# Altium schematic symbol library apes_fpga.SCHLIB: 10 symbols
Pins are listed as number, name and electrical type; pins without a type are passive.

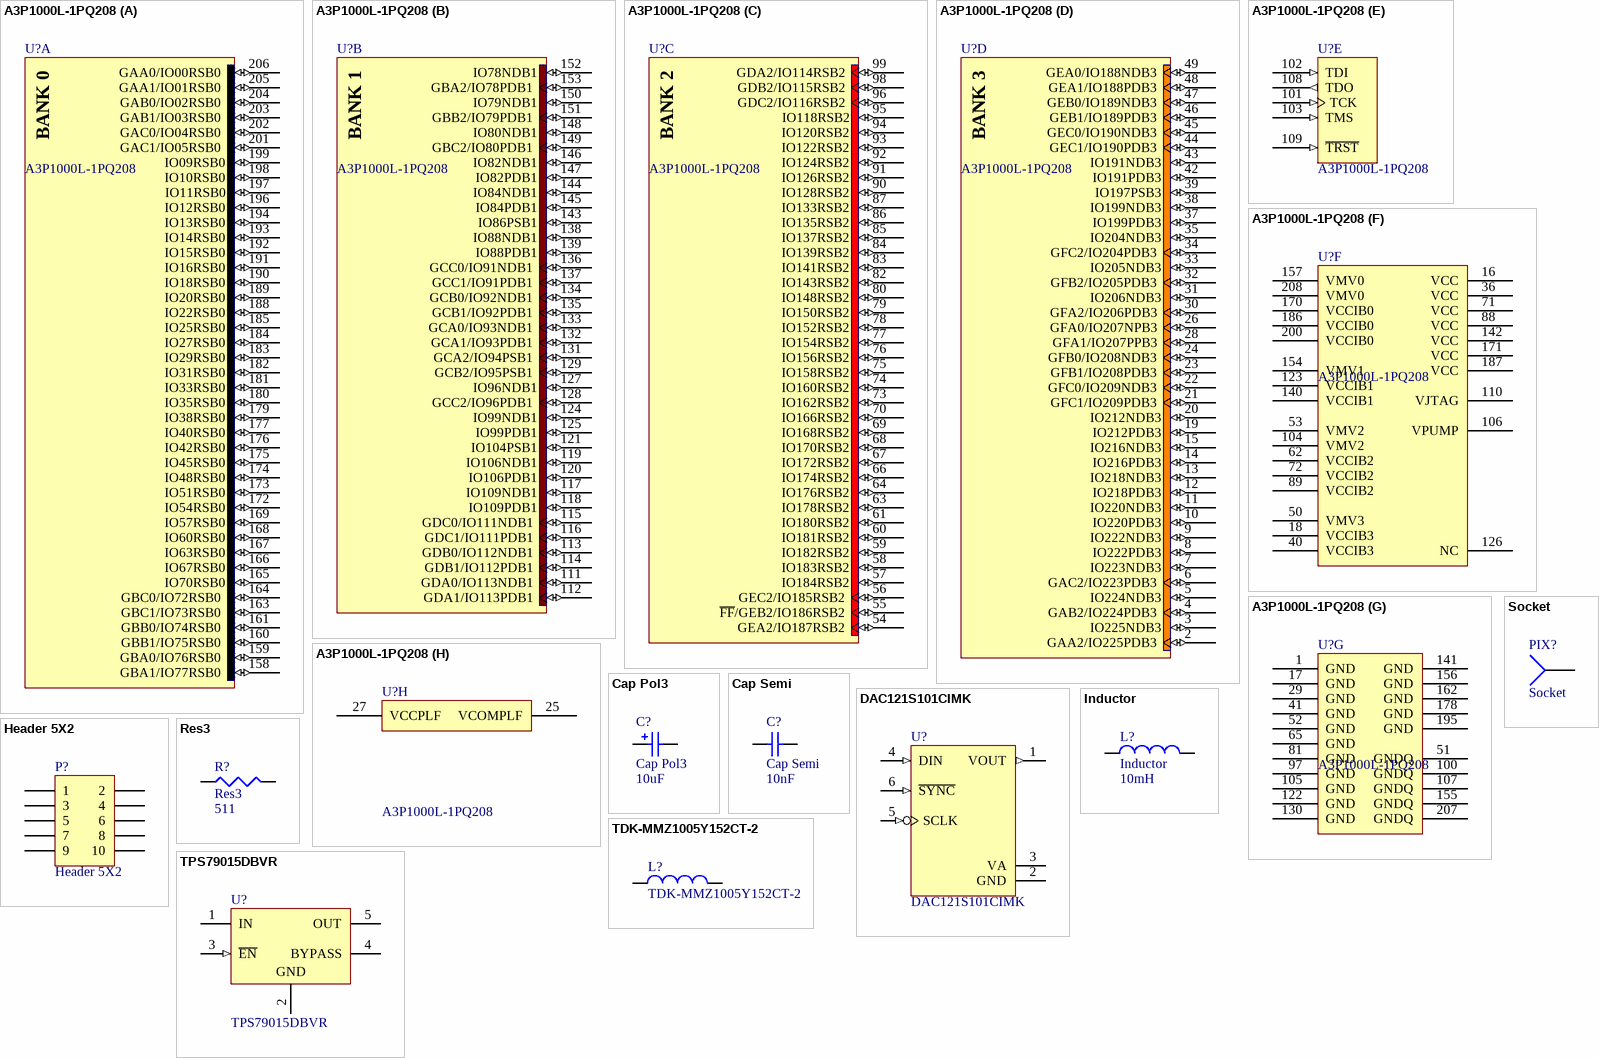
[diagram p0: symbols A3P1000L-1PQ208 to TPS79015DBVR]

## A3P1000L-1PQ208
designator U?
ProASIC3L Low-Power Flash Family FPGA, 154 User IOs, 1M System Gates, 144 Kbits RAM, 1 Kbit FlashROM, 1PLL, 208-Pin PQFP, Commercial Grade
footprint PQ208_N (Shrink QFP, 208-Leads, Body 28x28mm, Pitch 0.5mm, IPC Medium Density)
footprint PQ208_L (Shrink QFP, 208-Leads, Body 28x28mm, Pitch 0.5mm, IPC High Density)
footprint PQ208_M (Shrink QFP, 208-Leads, Body 28x28mm, Pitch 0.5mm, IPC Low Density)
part A pins: 158 GBA1/IO77RSB0 (io), 159 GBA0/IO76RSB0 (io), 160 GBB1/IO75RSB0 (io), 161 GBB0/IO74RSB0 (io), 163 GBC1/IO73RSB0 (io), 164 GBC0/IO72RSB0 (io), 165 IO70RSB0 (io), 166 IO67RSB0 (io), 167 IO63RSB0 (io), 168 IO60RSB0 (io), 169 IO57RSB0 (io), 172 IO54RSB0 (io), 173 IO51RSB0 (io), 174 IO48RSB0 (io), 175 IO45RSB0 (io), 176 IO42RSB0 (io), 177 IO40RSB0 (io), 179 IO38RSB0 (io), 180 IO35RSB0 (io), 181 IO33RSB0 (io), 182 IO31RSB0 (io), 183 IO29RSB0 (io), 184 IO27RSB0 (io), 185 IO25RSB0 (io), 188 IO22RSB0 (io), 189 IO20RSB0 (io), 190 IO18RSB0 (io), 191 IO16RSB0 (io), 192 IO15RSB0 (io), 193 IO14RSB0 (io), 194 IO13RSB0 (io), 196 IO12RSB0 (io), 197 IO11RSB0 (io), 198 IO10RSB0 (io), 199 IO09RSB0 (io), 201 GAC1/IO05RSB0 (io), 202 GAC0/IO04RSB0 (io), 203 GAB1/IO03RSB0 (io), 204 GAB0/IO02RSB0 (io), 205 GAA1/IO01RSB0 (io), 206 GAA0/IO00RSB0 (io)
part B pins: 111 GDA0/IO113NDB1 (io), 112 GDA1/IO113PDB1 (io), 113 GDB0/IO112NDB1 (io), 114 GDB1/IO112PDB1 (io), 115 GDC0/IO111NDB1 (io), 116 GDC1/IO111PDB1 (io), 117 IO109NDB1 (io), 118 IO109PDB1 (io), 119 IO106NDB1 (io), 120 IO106PDB1 (io), 121 IO104PSB1 (io), 124 IO99NDB1 (io), 125 IO99PDB1 (io), 127 IO96NDB1 (io), 128 GCC2/IO96PDB1 (io), 129 GCB2/IO95PSB1 (io), 131 GCA2/IO94PSB1 (io), 132 GCA1/IO93PDB1 (io), 133 GCA0/IO93NDB1 (io), 134 GCB0/IO92NDB1 (io), 135 GCB1/IO92PDB1 (io), 136 GCC0/IO91NDB1 (io), 137 GCC1/IO91PDB1 (io), 138 IO88NDB1 (io), 139 IO88PDB1 (io), 143 IO86PSB1 (io), 144 IO84NDB1 (io), 145 IO84PDB1 (io), 146 IO82NDB1 (io), 147 IO82PDB1 (io), 148 IO80NDB1 (io), 149 GBC2/IO80PDB1 (io), 150 IO79NDB1 (io), 151 GBB2/IO79PDB1 (io), 152 IO78NDB1 (io), 153 GBA2/IO78PDB1 (io)
part C pins: 54 GEA2/IO187RSB2 (io), 55 ~{FF}/GEB2/IO186RSB2 (io), 56 GEC2/IO185RSB2 (io), 57 IO184RSB2 (io), 58 IO183RSB2 (io), 59 IO182RSB2 (io), 60 IO181RSB2 (io), 61 IO180RSB2 (io), 63 IO178RSB2 (io), 64 IO176RSB2 (io), 66 IO174RSB2 (io), 67 IO172RSB2 (io), 68 IO170RSB2 (io), 69 IO168RSB2 (io), 70 IO166RSB2 (io), 73 IO162RSB2 (io), 74 IO160RSB2 (io), 75 IO158RSB2 (io), 76 IO156RSB2 (io), 77 IO154RSB2 (io), 78 IO152RSB2 (io), 79 IO150RSB2 (io), 80 IO148RSB2 (io), 82 IO143RSB2 (io), 83 IO141RSB2 (io), 84 IO139RSB2 (io), 85 IO137RSB2 (io), 86 IO135RSB2 (io), 87 IO133RSB2 (io), 90 IO128RSB2 (io), 91 IO126RSB2 (io), 92 IO124RSB2 (io), 93 IO122RSB2 (io), 94 IO120RSB2 (io), 95 IO118RSB2 (io), 96 GDC2/IO116RSB2 (io), 98 GDB2/IO115RSB2 (io), 99 GDA2/IO114RSB2 (io)
part D pins: 2 GAA2/IO225PDB3 (io), 3 IO225NDB3 (io), 4 GAB2/IO224PDB3 (io), 5 IO224NDB3 (io), 6 GAC2/IO223PDB3 (io), 7 IO223NDB3 (io), 8 IO222PDB3 (io), 9 IO222NDB3 (io), 10 IO220PDB3 (io), 11 IO220NDB3 (io), 12 IO218PDB3 (io), 13 IO218NDB3 (io), 14 IO216PDB3 (io), 15 IO216NDB3 (io), 19 IO212PDB3 (io), 20 IO212NDB3 (io), 21 GFC1/IO209PDB3 (io), 22 GFC0/IO209NDB3 (io), 23 GFB1/IO208PDB3 (io), 24 GFB0/IO208NDB3 (io), 26 GFA0/IO207NPB3 (io), 28 GFA1/IO207PPB3 (io), 30 GFA2/IO206PDB3 (io), 31 IO206NDB3 (io), 32 GFB2/IO205PDB3 (io), 33 IO205NDB3 (io), 34 GFC2/IO204PDB3 (io), 35 IO204NDB3 (io), 37 IO199PDB3 (io), 38 IO199NDB3 (io), 39 IO197PSB3 (io), 42 IO191PDB3 (io), 43 IO191NDB3 (io), 44 GEC1/IO190PDB3 (io), 45 GEC0/IO190NDB3 (io), 46 GEB1/IO189PDB3 (io), 47 GEB0/IO189NDB3 (io), 48 GEA1/IO188PDB3 (io), 49 GEA0/IO188NDB3 (io)
part E pins: 101 TCK (in), 102 TDI (in), 103 TMS (in), 108 TDO (out), 109 ~{TRST} (in)
part F pins: 16 VCC (power), 18 VCCIB3 (power), 36 VCC (power), 40 VCCIB3 (power), 50 VMV3 (power), 53 VMV2 (power), 62 VCCIB2 (power), 71 VCC (power), 72 VCCIB2 (power), 88 VCC (power), 89 VCCIB2 (power), 104 VMV2 (power), 106 VPUMP (power), 110 VJTAG (power), 123 VCCIB1 (power), 126 NC, 140 VCCIB1 (power), 142 VCC (power), 154 VMV1 (power), 157 VMV0 (power), 170 VCCIB0 (power), 171 VCC (power), 186 VCCIB0 (power), 187 VCC (power), 200 VCCIB0 (power), 208 VMV0 (power)
part G pins: 1 GND (power), 17 GND (power), 29 GND (power), 41 GND (power), 51 GNDQ (power), 52 GND (power), 65 GND (power), 81 GND (power), 97 GND (power), 100 GNDQ (power), 105 GND (power), 107 GNDQ (power), 122 GND (power), 130 GND (power), 141 GND (power), 155 GNDQ (power), 156 GND (power), 162 GND (power), 178 GND (power), 195 GND (power), 207 GNDQ (power)
part H pins: 25 VCOMPLF (power), 27 VCCPLF (power)

## Cap Pol3
designator C?  value 10uF
Polarized Capacitor (Surface Mount)
footprint C0805 (Chip Capacitor, Body 2.0x1.3mm, IPC High Density)
footprint 1812 (Chip Capacitor, Body 4.5x3.2mm, IPC High Density)
footprint 1825 (Chip Capacitor, Body 4.5x6.4mm, IPC High Density)
footprint C2225 (Chip Capacitor, Body 5.7x6.4mm, IPC High Density)
footprint 2220 (Chip Capacitor, Body 5.7x5.0mm, IPC High Density)
simulation model CAP (Capacitor)
signal-integrity model Cap Pol
pins: 1, 2
1 alternate drawing of the same symbol

## Cap Semi
designator C?  value 10nF
Capacitor (Semiconductor SIM Model)
footprint C1206 (Chip Capacitor, Body 3.2x1.6mm, IPC High Density)
footprint 0402 (Chip Capacitor, Body 1.0x0.5mm, IPC High Density)
footprint C2512 (Chip Capacitor, Body 2.54x1.27mm, IPC High Density)
footprint 1608[0603] (Chip Capacitor, Body 1.6x0.8mm, IPC High Density)
footprint C1210 (Chip Capacitor, Body 3.2x2.5mm, IPC High Density)
simulation model CAP (Semiconductor Capacitor)
signal-integrity model Cap Semi
pins: 1, 2

## DAC121S101CIMK
designator U?
12-Bit Micro Power Digital-to-Analog Converter with Rail-to-Rail Output, 6-pin Tiny SOT23; Manufacturer: National Semiconductor; PackageTopMarking: X61C*XTT; PowerWise: Y; CompType: D/A Converter
footprint MK06A_N (SOT23, 6-Leads, Body 3.0x1.7mm, Pitch 0.95mm, Lead Span 2.9mm, IPC Medium Density)
footprint MK06A_L (SOT23, 6-Leads, Body 3.0x1.7mm, Pitch 0.95mm, Lead Span 2.9mm, IPC High Density)
footprint MK06A_M (SOT23, 6-Leads, Body 3.0x1.7mm, Pitch 0.95mm, Lead Span 2.9mm, IPC Low Density)
pins: 1 VOUT (out), 2 GND (power), 3 VA (power), 4 DIN (in), 5 SCLK (in), 6 ~{SYNC} (in)

## Header 5X2
designator P?
Header, 5-Pin, Dual row
footprint HDR2X5 (Connector; Header; 5x2 Position)
signal-integrity model Connector
pins: 1, 2, 3, 4, 5, 6, 7, 8, 9, 10

## Inductor
designator L?  value 10mH
Code_IEC: 1005
footprint 0402-A (Chip Inductor, Body 1.0x0.5mm, IPC High Density)
footprint INDC1608L (Chip Inductor, Body 1.6x0.8mm, IPC High Density)
footprint 2029 (Chip Inductor, Body 2.0x1.2mm, IPC High Density)
footprint 0603 (Chip Inductor, Body 0.6x0.3mm, IPC High Density)
footprint INDC3216 (Chip Inductor, Body 3.2x1.6mm, IPC High Density)
footprint INDC4532 (Chip Inductor, Body 4.5x3.2mm, IPC High Density)
simulation model INDUCTOR (Inductor)
signal-integrity model Inductor
pins: 1, 2

## Res3
designator R?  value 511
Resistor
footprint J1-0603 (Chip Resistor, Body 1.6x0.8mm, IPC High Density)
footprint 14-1210 (Chip Resistor, Body 3.2x2.5mm, IPC High Density)
footprint 12Z-2010 (Chip Resistor, Body 5.0x2.5mm, IPC High Density)
footprint RESC6332 (Chip Resistor, Body 6.3x3.2mm, IPC High Density)
simulation model RESISTOR (Resistor)
signal-integrity model Res
pins: 1, 2

## Socket
designator PIX?
footprint PIN1 (Connector; Socket)
signal-integrity model Connector
pins: 1

## TDK-MMZ1005Y152CT-2
designator L?
footprint J1-0603
pins: 1, 2

## TPS79015DBVR
designator U?
Single Output Low Noise LDO, 50 mA, Fixed 1.5 V Output, 2.7 to 10 V Input, with Low IQ, 5-pin SOT-23 (DBV), -40 to 125 degC, Green (RoHS & no Sb/Br); Manufacturer: Texas Instruments; Fixed Output Options(V): 1.5; Iout(Max)(A): 0.05; Iq(Typ)(mA): 0.02; Rating: Catalog; SubFamily: Single Channel LDO; Vdo(Typ)(mV): 57; Vin(Max)(V): 10; Vin(Min)(V): 2.7
footprint TI-DBV5_N (SOT23, 5-Leads, Body 2.9x1.6mm, Pitch 0.95mm, IPC Medium Density)
footprint TI-DBV5_L (SOT23, 5-Leads, Body 2.9x1.6mm, Pitch 0.95mm, IPC High Density)
footprint TI-DBV5_M (SOT23, 5-Leads, Body 2.9x1.6mm, Pitch 0.95mm, IPC Low Density)
pins: 1 IN (power) "The IN terminal is the input to the device.", 2 GND (power) "Regulator ground", 3 ~{EN} (in) "The E\N\ terminal is an input which enables or shuts down the device. When E\N\ is a logic high, the device will be in shutdown mode. When E\N\ is a logic low, the device will be enabled.", 4 BYPASS "An external bypass capacitor, connected to this terminal, in conjunction with an internal resistor, creates a low-pass filter to further reduce regulator noise.", 5 OUT (power) "The OUT terminal is the regulated output of the device."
